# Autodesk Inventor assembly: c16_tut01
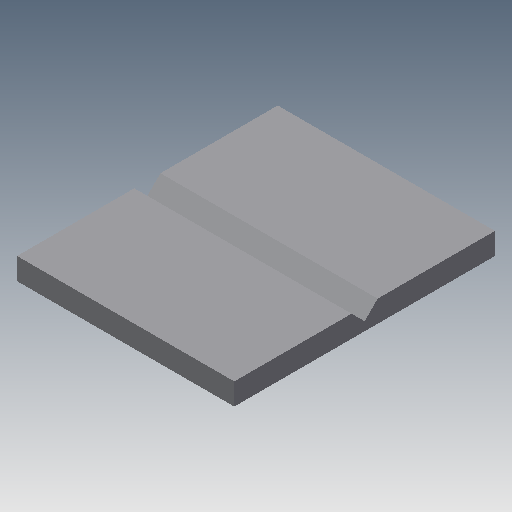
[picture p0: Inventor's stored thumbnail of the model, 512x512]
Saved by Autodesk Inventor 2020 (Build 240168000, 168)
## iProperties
Created: 2010-05
Part Number: c16_tut01
Document SubType Name: Weldment
Designer: CADSoft
Weld Material: Welded Aluminum-6061
Author: CADSoft
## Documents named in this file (2)
- D:\Autodesk Inventor_2020\Resources\Resources\Inventor_2020_tut\Inventor_2020_tut\c16_Inv_2020_tut\c16_Inv_tut_2020\c16_tut01\c16_tut01.iam
- D:\Autodesk Inventor_2020\Resources\Resources\Inventor_2020_tut\Inventor_2020_tut\c16_Inv_2020_tut\c16_Inv_tut_2020\c16_tut01\Plate.ipt
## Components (2 placed, 1 different names)
1. Plate:1 — Mate:1, Flush:1, Flush:2
2. Plate:2 — Mate:1, Flush:1, Flush:2
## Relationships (3: Flush 2, Mate 1)
- Mate:1: Plate:1 ↔ Plate:2
- Flush:1: Plate:1 ↔ Plate:2
- Flush:2: Plate:1 ↔ Plate:2
